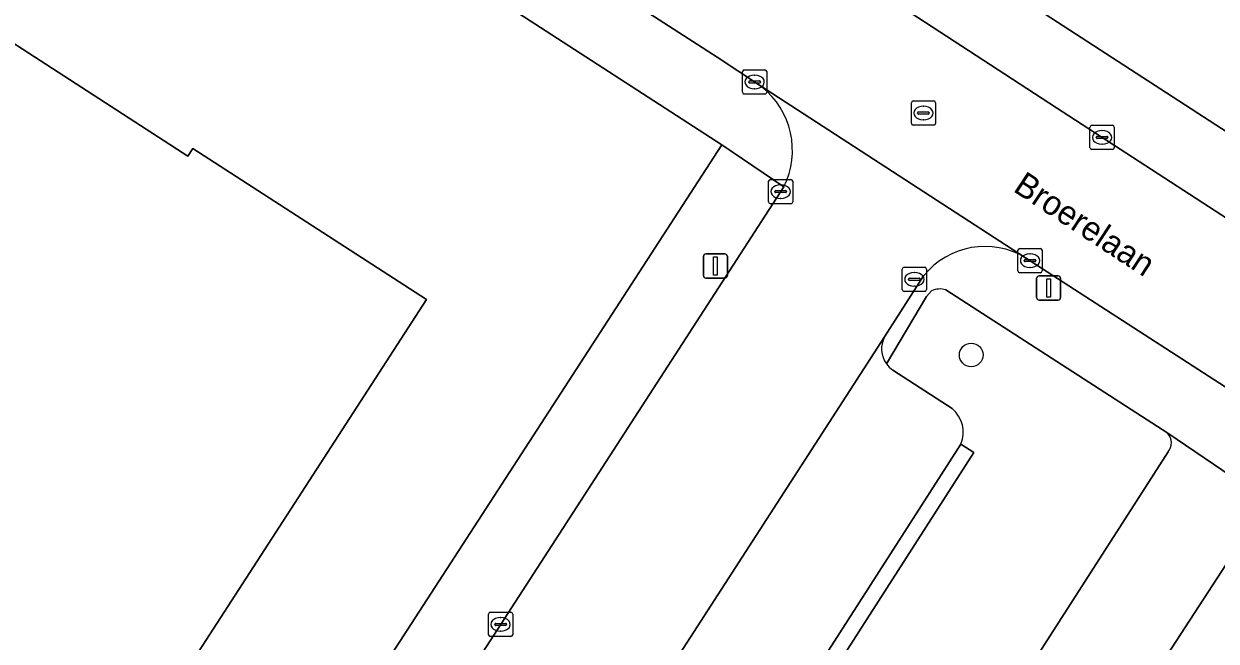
# Model space of a CAD drawing. Extents: x 161139 to 161601, y 381708 to 382245.
# Drawn here: x 161469.39 to 161518.67, y 382022.6 to 382048.13 of the extents above; entities that cross this region are included whole.
import ezdxf

# ---------------------------------------------------------------- set-up
doc = ezdxf.new("R2010")
doc.units = 0
for name, color, linetype in [('IMGEO_Boom', 7, 'Continuous'), ('IMGEO_Erf', 7, 'Continuous'), ('IMGEO_Groenvoorziening', 7, 'Continuous'), ('IMGEO_Kolk', 7, 'Continuous'), ('IMGEO_Lichtmast', 7, 'Continuous'), ('IMGEO_Openbare_ruimte_label', 7, 'Continuous'), ('IMGEO_Pand', 7, 'Continuous'), ('IMGEO_Parkeervlak_open', 7, 'Continuous'), ('IMGEO_Rijbaan_lokaal_open', 7, 'Continuous'), ('IMGEO_Rioolput', 7, 'Continuous'), ('IMGEO_Voetpad_open', 7, 'Continuous')]:
    doc.layers.add(name, color=color, linetype=linetype)

msp = doc.modelspace()

# ---------------------------------------------------------------- linework, layer by layer
at = {"layer": 'IMGEO_Boom'}
msp.add_circle((161508.547, 382034.432), 0.489, dxfattribs=at)
at = {"layer": 'IMGEO_Erf'}
for points in [[(161553.295, 382144.911), (161544.61, 382147.101), (161500, 382158.072), (161477.956, 382163.494), (161457.897, 382168.303), (161418.52, 382178.097), (161389.844, 382185.251), (161387.058, 382185.651), (161384.186, 382184.996), (161381.949, 382183.375), (161380.259, 382181.034), (161377.586, 382172.934), (161374.321, 382163.969), (161372.26, 382158.835), (161369.98, 382153.637), (161365.084, 382143.565), (161365.175, 382143.293), (161389.855, 382127.317), (161408.789, 382114.947), (161450.498, 382088.211), (161500, 382056.07), (161523.437, 382040.853), (161561.628, 382099.383), (161581.409, 382129.761)], [(161320.525, 382089.631), (161313.623, 382083.997), (161443.483, 382000), (161462.38, 381987.777), (161470.3, 382000), (161498.24, 382043.117), (161359.011, 382133.266)]]:
    msp.add_lwpolyline(points, dxfattribs=at)
msp.add_lwpolyline([(161465.14, 382043.824), (161467.861, 382048.029), (161476.169, 382042.655), (161476.375, 382042.973), (161486.031, 382036.726), (161463.237, 382001.496), (161453.51, 382007.789), (161458.187, 382015.018), (161459.285, 382014.308), (161462.86, 382019.835), (161460.857, 382021.131), (161461.57, 382022.233), (161460.898, 382022.668), (161459.22, 382020.074), (161456.379, 382021.912), (161458.057, 382024.506), (161451.086, 382029.016), (161453.802, 382033.215), (161455.991, 382036.598), (161466.421, 382029.851), (161466.963, 382030.689), (161462.496, 382033.579), (161463.339, 382034.883), (161460.531, 382036.7)], close=True, dxfattribs=at)
at = {"layer": 'IMGEO_Groenvoorziening'}
for points in [[(161506.907, 382037.088), (161506.701, 382036.855), (161505.041, 382034.066)], [(161516.669, 382031.191), (161507.502, 382037.129)], [(161505.308, 382033.806), (161507.761, 382032.211)], [(161508.122, 382030.748), (161508.66, 382030.403), (161496.714, 382011.755), (161502.377, 382008.114), (161503.136, 382009.288), (161516.685, 382030.422)], [(161521.27, 382028.087), (161520.791, 382028.402), (161505.482, 382004.864), (161509.353, 382002.408), (161522.399, 382022.591)]]:
    msp.add_lwpolyline(points, dxfattribs=at)
for centre, radius, start, end in [((161507.263, 382036.263), 0.898, 74.5543, 113.3294), ((161505.897, 382034.678), 1.053, 215.5671, 235.9549), ((161506.949, 382031.235), 1.27, 337.4566, 50.2655), ((161516.236, 382030.797), 0.585, 320.1315, 42.2524)]:
    msp.add_arc(centre, radius, start, end, dxfattribs=at)
at = {"layer": 'IMGEO_Kolk'}
for p, q in [((161499.094, 382045.296), (161499.094, 382046.148)), ((161499.169, 382046.222), (161500.021, 382046.222)), ((161499.582, 382046.002), (161499.607, 382046.002)), ((161500.095, 382046.148), (161500.095, 382045.296)), ((161499.353, 382045.716), (161499.353, 382045.728)), ((161499.791, 382045.679), (161499.393, 382045.679)), ((161499.396, 382045.765), (161499.794, 382045.765)), ((161499.605, 382045.442), (161499.58, 382045.442)), ((161499.837, 382045.728), (161499.837, 382045.716)), ((161500.021, 382045.222), (161499.169, 382045.222)), ((161513.532, 382043.93), (161514.384, 382043.93)), ((161513.457, 382043.004), (161513.457, 382043.856)), ((161513.716, 382043.424), (161513.716, 382043.436)), ((161513.759, 382043.473), (161514.157, 382043.473)), ((161513.945, 382043.71), (161513.97, 382043.71)), ((161514.2, 382043.436), (161514.2, 382043.424)), ((161514.458, 382043.856), (161514.458, 382043.004)), ((161514.384, 382042.93), (161513.532, 382042.93)), ((161514.154, 382043.387), (161513.756, 382043.387)), ((161513.968, 382043.15), (161513.943, 382043.15)), ((161500.17, 382040.761), (161500.17, 382041.613)), ((161500.245, 382041.687), (161501.097, 382041.687)), ((161500.658, 382041.467), (161500.683, 382041.467)), ((161501.171, 382041.613), (161501.171, 382040.761)), ((161500.429, 382041.181), (161500.429, 382041.193)), ((161500.867, 382041.144), (161500.469, 382041.144)), ((161500.472, 382041.23), (161500.87, 382041.23)), ((161500.913, 382041.193), (161500.913, 382041.181)), ((161501.097, 382040.687), (161500.245, 382040.687)), ((161500.681, 382040.907), (161500.656, 382040.907)), ((161510.478, 382037.909), (161510.478, 382038.761)), ((161510.553, 382038.835), (161511.405, 382038.835)), ((161510.966, 382038.615), (161510.991, 382038.615)), ((161511.479, 382038.761), (161511.479, 382037.909)), ((161505.772, 382038.06), (161506.624, 382038.06)), ((161510.737, 382038.329), (161510.737, 382038.341)), ((161511.175, 382038.292), (161510.777, 382038.292)), ((161510.78, 382038.378), (161511.178, 382038.378)), ((161510.989, 382038.055), (161510.964, 382038.055)), ((161511.221, 382038.341), (161511.221, 382038.329)), ((161505.697, 382037.134), (161505.697, 382037.986)), ((161505.956, 382037.554), (161505.956, 382037.566)), ((161506.394, 382037.517), (161505.996, 382037.517)), ((161505.999, 382037.603), (161506.397, 382037.603)), ((161506.185, 382037.84), (161506.21, 382037.84)), ((161506.44, 382037.566), (161506.44, 382037.554)), ((161506.698, 382037.986), (161506.698, 382037.134)), ((161511.405, 382037.835), (161510.553, 382037.835)), ((161506.624, 382037.06), (161505.772, 382037.06)), ((161506.208, 382037.28), (161506.183, 382037.28)), ((161488.595, 382022.863), (161488.595, 382023.715)), ((161488.67, 382023.789), (161489.522, 382023.789)), ((161489.596, 382023.715), (161489.596, 382022.863)), ((161488.854, 382023.283), (161488.854, 382023.295)), ((161489.292, 382023.246), (161488.894, 382023.246)), ((161488.897, 382023.332), (161489.295, 382023.332)), ((161489.083, 382023.569), (161489.108, 382023.569)), ((161489.338, 382023.295), (161489.338, 382023.283)), ((161489.522, 382022.789), (161488.67, 382022.789)), ((161489.106, 382023.009), (161489.081, 382023.009))]:
    msp.add_line(p, q, dxfattribs=at)
for points in [[(161499.094, 382045.296), (161499.094, 382046.148)], [(161499.169, 382046.222), (161500.021, 382046.222)], [(161500.095, 382046.148), (161500.095, 382045.296)], [(161500.021, 382045.222), (161499.169, 382045.222)], [(161513.532, 382043.93), (161514.384, 382043.93)], [(161513.457, 382043.004), (161513.457, 382043.856)], [(161514.458, 382043.856), (161514.458, 382043.004)], [(161514.384, 382042.93), (161513.532, 382042.93)], [(161500.17, 382040.761), (161500.17, 382041.613)], [(161500.245, 382041.687), (161501.097, 382041.687)], [(161501.171, 382041.613), (161501.171, 382040.761)], [(161501.097, 382040.687), (161500.245, 382040.687)], [(161510.478, 382037.909), (161510.478, 382038.761)], [(161510.553, 382038.835), (161511.405, 382038.835)], [(161511.479, 382038.761), (161511.479, 382037.909)], [(161505.772, 382038.06), (161506.624, 382038.06)], [(161505.697, 382037.134), (161505.697, 382037.986)], [(161506.698, 382037.986), (161506.698, 382037.134)], [(161511.405, 382037.835), (161510.553, 382037.835)], [(161506.624, 382037.06), (161505.772, 382037.06)], [(161488.595, 382022.863), (161488.595, 382023.715)], [(161488.67, 382023.789), (161489.522, 382023.789)], [(161489.596, 382023.715), (161489.596, 382022.863)], [(161489.522, 382022.789), (161488.67, 382022.789)]]:
    msp.add_lwpolyline(points, dxfattribs=at)
for centre, radius, start, end in [((161499.171, 382046.146), 0.0765, 91.552, 178.448), ((161499.171, 382046.146), 0.0765, 91.552, 178.448), ((161500.019, 382046.146), 0.0765, 1.552, 88.448), ((161500.019, 382046.146), 0.0765, 1.552, 88.448), ((161499.393, 382045.725), 0.0403, 85.8775, 175.7526), ((161499.39, 382045.715), 0.0366, 178.938, 274.7102), ((161499.794, 382045.722), 0.043, 264.8664, 352.4533), ((161499.798, 382045.727), 0.0386, 1.7309, 96.639), ((161499.171, 382045.298), 0.0765, 181.552, 268.448), ((161499.171, 382045.298), 0.0765, 181.552, 268.448), ((161500.019, 382045.298), 0.0765, 271.552, 358.448), ((161500.019, 382045.298), 0.0765, 271.552, 358.448), ((161513.534, 382043.854), 0.0765, 91.552, 178.448), ((161513.534, 382043.854), 0.0765, 91.552, 178.448), ((161514.382, 382043.854), 0.0765, 1.552, 88.448), ((161514.382, 382043.854), 0.0765, 1.552, 88.448), ((161513.756, 382043.433), 0.0403, 85.8775, 175.7526), ((161513.753, 382043.423), 0.0366, 178.938, 274.7102), ((161514.157, 382043.43), 0.043, 264.8664, 352.4533), ((161514.161, 382043.435), 0.0386, 1.7309, 96.639), ((161513.534, 382043.006), 0.0765, 181.552, 268.448), ((161513.534, 382043.006), 0.0765, 181.552, 268.448), ((161514.382, 382043.006), 0.0765, 271.552, 358.448), ((161514.382, 382043.006), 0.0765, 271.552, 358.448), ((161500.247, 382041.611), 0.0765, 91.552, 178.448), ((161500.247, 382041.611), 0.0765, 91.552, 178.448), ((161501.095, 382041.611), 0.0765, 1.552, 88.448), ((161501.095, 382041.611), 0.0765, 1.552, 88.448), ((161500.469, 382041.19), 0.0403, 85.8775, 175.7526), ((161500.466, 382041.18), 0.0366, 178.938, 274.7102), ((161500.87, 382041.187), 0.043, 264.8664, 352.4533), ((161500.874, 382041.192), 0.0386, 1.7309, 96.639), ((161500.247, 382040.763), 0.0765, 181.552, 268.448), ((161500.247, 382040.763), 0.0765, 181.552, 268.448), ((161501.095, 382040.763), 0.0765, 271.552, 358.448), ((161501.095, 382040.763), 0.0765, 271.552, 358.448), ((161510.555, 382038.759), 0.0765, 91.552, 178.448), ((161510.555, 382038.759), 0.0765, 91.552, 178.448), ((161511.403, 382038.759), 0.0765, 1.552, 88.448), ((161511.403, 382038.759), 0.0765, 1.552, 88.448), ((161505.774, 382037.984), 0.0765, 91.552, 178.448), ((161505.774, 382037.984), 0.0765, 91.552, 178.448), ((161506.622, 382037.984), 0.0765, 1.552, 88.448), ((161506.622, 382037.984), 0.0765, 1.552, 88.448), ((161510.777, 382038.338), 0.0403, 85.8775, 175.7526), ((161510.774, 382038.328), 0.0366, 178.938, 274.7102), ((161511.178, 382038.335), 0.043, 264.8664, 352.4533), ((161511.182, 382038.34), 0.0386, 1.7309, 96.639), ((161505.996, 382037.563), 0.0403, 85.8775, 175.7526), ((161505.993, 382037.553), 0.0366, 178.938, 274.7102), ((161506.397, 382037.56), 0.043, 264.8664, 352.4533), ((161506.401, 382037.565), 0.0386, 1.7309, 96.639), ((161510.555, 382037.911), 0.0765, 181.552, 268.448), ((161510.555, 382037.911), 0.0765, 181.552, 268.448), ((161511.403, 382037.911), 0.0765, 271.552, 358.448), ((161511.403, 382037.911), 0.0765, 271.552, 358.448), ((161505.774, 382037.136), 0.0765, 181.552, 268.448), ((161505.774, 382037.136), 0.0765, 181.552, 268.448), ((161506.622, 382037.136), 0.0765, 271.552, 358.448), ((161506.622, 382037.136), 0.0765, 271.552, 358.448), ((161488.672, 382023.713), 0.0765, 91.552, 178.448), ((161488.672, 382023.713), 0.0765, 91.552, 178.448), ((161489.52, 382023.713), 0.0765, 1.552, 88.448), ((161489.52, 382023.713), 0.0765, 1.552, 88.448), ((161488.894, 382023.292), 0.0403, 85.8775, 175.7526), ((161488.891, 382023.282), 0.0366, 178.938, 274.7102), ((161489.295, 382023.289), 0.043, 264.8664, 352.4533), ((161489.299, 382023.294), 0.0386, 1.7309, 96.639), ((161488.672, 382022.865), 0.0765, 181.552, 268.448), ((161488.672, 382022.865), 0.0765, 181.552, 268.448), ((161489.52, 382022.865), 0.0765, 271.552, 358.448), ((161489.52, 382022.865), 0.0765, 271.552, 358.448)]:
    msp.add_arc(centre, radius, start, end, dxfattribs=at)
for centre, major_axis, ratio, start_param, end_param in [((161499.581, 382045.722), (-0.387, 0.002), 0.722429, 4.712389, 7.853982), ((161499.606, 382045.722), (-0.39, 0.002), 0.717154, 1.570796, 4.712389), ((161513.944, 382043.43), (-0.387, 0.002), 0.722429, 4.712389, 7.853982), ((161513.969, 382043.43), (-0.39, 0.002), 0.717154, 1.570796, 4.712389), ((161500.657, 382041.187), (-0.387, 0.002), 0.722429, 4.712389, 7.853982), ((161500.682, 382041.187), (-0.39, 0.002), 0.717154, 1.570796, 4.712389), ((161510.965, 382038.335), (-0.387, 0.002), 0.722429, 4.712389, 7.853982), ((161510.99, 382038.335), (-0.39, 0.002), 0.717154, 1.570796, 4.712389), ((161506.184, 382037.56), (-0.387, 0.002), 0.722429, 4.712389, 7.853982), ((161506.209, 382037.56), (-0.39, 0.002), 0.717154, 1.570796, 4.712389), ((161489.082, 382023.289), (-0.387, 0.002), 0.722429, 4.712389, 7.853982), ((161489.107, 382023.289), (-0.39, 0.002), 0.717154, 1.570796, 4.712389)]:
    msp.add_ellipse(centre, major_axis=major_axis, ratio=ratio, start_param=start_param, end_param=end_param, dxfattribs=at)
at = {"layer": 'IMGEO_Lichtmast'}
for p, q in [((161497.479, 382037.712), (161497.479, 382038.512)), ((161497.479, 382038.512), (161497.479, 382037.712)), ((161497.579, 382038.612), (161498.369, 382038.612)), ((161498.369, 382038.612), (161497.579, 382038.612)), ((161498.469, 382038.512), (161498.469, 382037.712)), ((161498.469, 382037.712), (161498.469, 382038.512)), ((161498.369, 382037.612), (161497.579, 382037.612)), ((161497.579, 382037.612), (161498.369, 382037.612)), ((161511.252, 382036.803), (161511.252, 382037.603)), ((161511.252, 382037.603), (161511.252, 382036.803)), ((161511.352, 382037.703), (161512.142, 382037.703)), ((161512.142, 382037.703), (161511.352, 382037.703)), ((161512.242, 382037.603), (161512.242, 382036.803)), ((161512.242, 382036.803), (161512.242, 382037.603)), ((161512.142, 382036.703), (161511.352, 382036.703)), ((161511.352, 382036.703), (161512.142, 382036.703))]:
    msp.add_line(p, q, dxfattribs=at)
for points in [[(161497.899, 382038.487), (161498.049, 382038.487), (161498.049, 382037.737), (161497.899, 382037.737), (161497.899, 382038.487)], [(161511.672, 382037.578), (161511.822, 382037.578), (161511.822, 382036.828), (161511.672, 382036.828), (161511.672, 382037.578)]]:
    msp.add_lwpolyline(points, dxfattribs=at)
for centre, start, end in [((161497.579, 382038.512), 90, 180), ((161497.579, 382038.512), 90, 180), ((161498.369, 382038.512), 0, 90), ((161498.369, 382038.512), 360, 90), ((161497.579, 382037.712), 180, 270), ((161497.579, 382037.712), 180, 270), ((161498.369, 382037.712), 270, 0), ((161498.369, 382037.712), 270, 0), ((161511.352, 382037.603), 90, 180), ((161511.352, 382037.603), 90, 180), ((161512.142, 382037.603), 0, 90), ((161512.142, 382037.603), 360, 90), ((161511.352, 382036.803), 180, 270), ((161511.352, 382036.803), 180, 270), ((161512.142, 382036.803), 270, 0), ((161512.142, 382036.803), 270, 0)]:
    msp.add_arc(centre, 0.1, start, end, dxfattribs=at)
at = {"layer": 'IMGEO_Pand'}
msp.add_lwpolyline([(161486.031, 382036.726), (161476.375, 382042.973), (161476.169, 382042.655), (161467.861, 382048.029), (161465.14, 382043.824), (161460.531, 382036.7), (161463.339, 382034.883), (161462.496, 382033.579), (161466.963, 382030.689), (161466.421, 382029.851), (161455.991, 382036.598), (161453.802, 382033.215), (161451.086, 382029.016), (161458.057, 382024.506), (161456.379, 382021.912), (161459.22, 382020.074), (161460.898, 382022.668), (161461.57, 382022.233), (161460.857, 382021.131), (161462.86, 382019.835), (161459.285, 382014.308), (161458.187, 382015.018), (161453.51, 382007.789), (161463.237, 382001.496)], close=True, dxfattribs=at)
at = {"layer": 'IMGEO_Parkeervlak_open'}
for points in [[(161504.966, 382035.175), (161491.489, 382014.315)], [(161507.761, 382032.211), (161505.308, 382033.806)], [(161496.841, 382013.134), (161508.122, 382030.748)]]:
    msp.add_lwpolyline(points, dxfattribs=at)
for centre, radius, start, end in [((161505.9, 382034.681), 1.057, 152.1353, 215.6026), ((161505.897, 382034.678), 1.053, 215.5671, 235.9549), ((161506.949, 382031.235), 1.27, 337.4566, 50.2655)]:
    msp.add_arc(centre, radius, start, end, dxfattribs=at)
at = {"layer": 'IMGEO_Rijbaan_lokaal_open'}
for points in [[(161521.765, 382038.348), (161512.078, 382044.654), (161498.469, 382053.534), (161494.669, 382055.998), (161485.554, 382061.86), (161483.251, 382063.426), (161480.028, 382065.466), (161471.488, 382070.983), (161468.287, 382073.003), (161467.324, 382073.702), (161460.192, 382078.284), (161453.24, 382082.778), (161444.055, 382088.754), (161440.905, 382090.804), (161426.931, 382099.82), (161420.597, 382103.968), (161416.21, 382106.739), (161403.197, 382115.21)], [(161398.574, 382111.058), (161401.761, 382109.008), (161415.306, 382100.289), (161421.669, 382096.147), (161435.549, 382087.163), (161442.527, 382082.644), (161453.542, 382075.54), (161460.477, 382071.037), (161473.195, 382062.836), (161477.592, 382059.945), (161498.051, 382046.741), (161499.796, 382045.589), (161510.796, 382038.454), (161522.385, 382030.943)], [(161510.796, 382038.454), (161499.796, 382045.589), (161499.84, 382045.557), (161499.883, 382045.525)], [(161500.799, 382041.385), (161464.955, 381985.959)], [(161485.898, 382005.698), (161491.489, 382014.315), (161504.966, 382035.175), (161506.503, 382037.599), (161506.547, 382037.659), (161506.592, 382037.718)]]:
    msp.add_lwpolyline(points, dxfattribs=at)
for centre, radius, start, end in [((161497.807, 382042.894), 3.351, 333.2345, 51.7176), ((161509.118, 382035.664), 3.256, 58.977, 140.8834)]:
    msp.add_arc(centre, radius, start, end, dxfattribs=at)
at = {"layer": 'IMGEO_Rioolput'}
for p, q in [((161506.148, 382044.937), (161507, 382044.937)), ((161506.073, 382044.011), (161506.073, 382044.863)), ((161506.332, 382044.431), (161506.332, 382044.443)), ((161506.375, 382044.48), (161506.773, 382044.48)), ((161506.561, 382044.717), (161506.586, 382044.717)), ((161506.816, 382044.443), (161506.816, 382044.431)), ((161507.074, 382044.863), (161507.074, 382044.011)), ((161507, 382043.937), (161506.148, 382043.937)), ((161506.77, 382044.394), (161506.372, 382044.394)), ((161506.584, 382044.157), (161506.559, 382044.157))]:
    msp.add_line(p, q, dxfattribs=at)
for points in [[(161506.148, 382044.937), (161507, 382044.937)], [(161506.073, 382044.011), (161506.073, 382044.863)], [(161507.074, 382044.863), (161507.074, 382044.011)], [(161507, 382043.937), (161506.148, 382043.937)]]:
    msp.add_lwpolyline(points, dxfattribs=at)
for centre, radius, start, end in [((161506.15, 382044.861), 0.0765, 91.552, 178.448), ((161506.15, 382044.861), 0.0765, 91.552, 178.448), ((161506.998, 382044.861), 0.0765, 1.552, 88.448), ((161506.998, 382044.861), 0.0765, 1.552, 88.448), ((161506.372, 382044.44), 0.0403, 85.8775, 175.7526), ((161506.369, 382044.43), 0.0366, 178.938, 274.7102), ((161506.773, 382044.437), 0.043, 264.8664, 352.4533), ((161506.777, 382044.442), 0.0386, 1.7309, 96.639), ((161506.15, 382044.013), 0.0765, 181.552, 268.448), ((161506.15, 382044.013), 0.0765, 181.552, 268.448), ((161506.998, 382044.013), 0.0765, 271.552, 358.448), ((161506.998, 382044.013), 0.0765, 271.552, 358.448)]:
    msp.add_arc(centre, radius, start, end, dxfattribs=at)
for centre, major_axis, ratio, start_param, end_param in [((161506.56, 382044.437), (-0.387, 0.002), 0.722429, 4.712389, 7.853982), ((161506.585, 382044.437), (-0.39, 0.002), 0.717154, 1.570796, 4.712389)]:
    msp.add_ellipse(centre, major_axis=major_axis, ratio=ratio, start_param=start_param, end_param=end_param, dxfattribs=at)
at = {"layer": 'IMGEO_Voetpad_open'}
for points in [[(161421.669, 382096.147), (161415.306, 382100.289), (161401.761, 382109.008), (161398.574, 382111.058), (161389.569, 382116.981), (161386.277, 382119.018), (161382.915, 382121.211), (161379.746, 382123.279), (161360.833, 382135.554), (161359.011, 382133.266), (161498.24, 382043.117), (161500.799, 382041.385)], [(161403.197, 382115.21), (161416.21, 382106.739), (161420.597, 382103.968), (161426.931, 382099.82), (161440.905, 382090.804), (161444.055, 382088.754), (161453.24, 382082.778), (161460.192, 382078.284), (161467.324, 382073.702), (161468.287, 382073.003), (161471.488, 382070.983), (161480.028, 382065.466), (161483.251, 382063.426), (161485.554, 382061.86), (161494.669, 382055.998), (161498.469, 382053.534), (161512.078, 382044.654), (161521.765, 382038.348), (161525.596, 382035.854), (161527.949, 382034.358)], [(161499.883, 382045.525), (161499.84, 382045.557), (161499.796, 382045.589), (161498.051, 382046.741), (161477.592, 382059.945), (161473.195, 382062.836), (161460.477, 382071.037), (161453.542, 382075.54), (161442.527, 382082.644), (161435.549, 382087.163), (161421.669, 382096.147)], [(161528.309, 382037.772), (161526.784, 382038.653), (161525.518, 382039.495), (161523.437, 382040.853), (161500, 382056.07), (161450.498, 382088.211)], [(161524.371, 382029.618), (161522.385, 382030.943), (161510.796, 382038.454)], [(161506.592, 382037.718), (161506.547, 382037.659), (161506.503, 382037.599), (161504.966, 382035.175)], [(161505.041, 382034.066), (161506.701, 382036.855), (161506.907, 382037.088)], [(161507.502, 382037.129), (161516.669, 382031.191), (161520.791, 382028.402), (161521.27, 382028.087)], [(161526.187, 382027.747), (161522.604, 382022.847), (161522.399, 382022.591), (161509.353, 382002.408), (161505.482, 382004.864), (161520.791, 382028.402), (161516.669, 382031.191)], [(161495.645, 382012.744), (161495.494, 382012.545), (161496.714, 382011.755), (161508.66, 382030.403), (161508.122, 382030.748), (161496.841, 382013.134)], [(161516.685, 382030.422), (161503.136, 382009.288), (161502.377, 382008.114), (161496.146, 381998.479), (161495.145, 381996.879), (161481.528, 381976.053)]]:
    msp.add_lwpolyline(points, dxfattribs=at)
msp.add_lwpolyline([(161500.799, 382041.385), (161498.24, 382043.117), (161470.3, 382000), (161462.38, 381987.777), (161464.955, 381985.959)], close=True, dxfattribs=at)
for centre, radius, start, end in [((161497.807, 382042.894), 3.351, 333.2345, 51.7176), ((161509.118, 382035.664), 3.256, 58.977, 140.8834), ((161507.263, 382036.263), 0.898, 74.5543, 113.3294), ((161505.9, 382034.681), 1.057, 152.1353, 215.6026), ((161516.236, 382030.797), 0.585, 320.1315, 42.2524)]:
    msp.add_arc(centre, radius, start, end, dxfattribs=at)

# ---------------------------------------------------------------- texts
at = {"layer": 'IMGEO_Openbare_ruimte_label'}
msp.add_text('Broerelaan', height=1, rotation=326.7072, dxfattribs=at).set_placement((161510.238, 382041.228))

doc.saveas('drawing.dxf')
